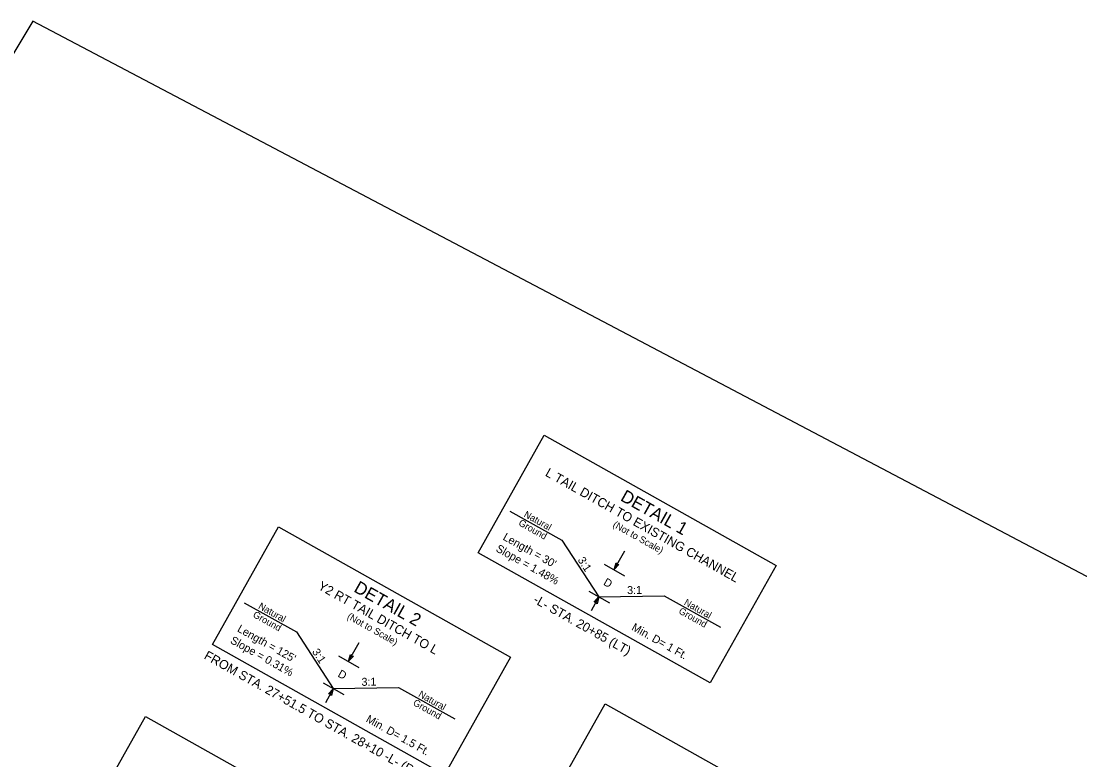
# Model space of a CAD drawing. Extents: x 2283629 to 2286552, y 529718 to 531440.
# Drawn here: x 2284113 to 2284634, y 531076 to 531440 of the extents above; entities that cross this region are included whole.
import ezdxf

# ---------------------------------------------------------------- set-up
doc = ezdxf.new("R2010")
doc.units = 0
for name, color, linetype in [('_CIVIL_CONSTRUCTION', 7, 'Continuous'), ('P_NCDOT_Terrain_Breakline', 7, 'Continuous'), ('P_NCDOT_Terrain_Hole', 7, 'Continuous')]:
    doc.layers.add(name, color=color, linetype=linetype)

msp = doc.modelspace()

# ---------------------------------------------------------------- linework, layer by layer
at = {"layer": '_CIVIL_CONSTRUCTION'}
msp.add_lwpolyline([(2284118.64, 531439.85), (2283629.48, 530625.47), (2284052.7, 530374.01), (2284693.86, 529987.87), (2284931.04, 529916.94), (2285004.15, 530031.44), (2284997.45, 530131.22), (2285008.79, 530131.98), (2285237.08, 530763.31), (2284930.09, 531012.33)], close=True, dxfattribs=at)
at = {"layer": 'P_NCDOT_Terrain_Breakline'}
for points in [[(2284400.44, 531103.96), (2284526.11, 531033.42), (2284494.1, 530976.4), (2284368.43, 531046.94), (2284400.44, 531103.96)], [(2284174.2, 531097.74), (2284299.87, 531027.2), (2284267.86, 530970.18), (2284142.19, 531040.72), (2284174.2, 531097.74)]]:
    msp.add_lwpolyline(points, dxfattribs=at)
at = {"layer": 'P_NCDOT_Terrain_Hole'}
for p, q in [((2284404.86, 531169.95), (2284410.02, 531179.14)), ((2284399.84, 531172.59), (2284409.93, 531166.92)), ((2284392.38, 531159.29), (2284402.47, 531153.63)), ((2284397.29, 531156.47), (2284393.44, 531149.6)), ((2284274.13, 531124.81), (2284279.29, 531134)), ((2284269.11, 531127.44), (2284279.2, 531121.78)), ((2284261.65, 531114.15), (2284271.74, 531108.48)), ((2284266.56, 531111.33), (2284262.71, 531104.46))]:
    msp.add_line(p, q, dxfattribs=at)
for points in [[(2284370.4, 531236.09), (2284484.57, 531172), (2284452.1, 531114.16), (2284337.93, 531178.25), (2284370.4, 531236.09)], [(2284353.49, 531198.72), (2284379.12, 531184.42), (2284397.32, 531156.52), (2284429.45, 531157.08), (2284457.17, 531141.63)], [(2284239.67, 531190.94), (2284353.84, 531126.86), (2284321.37, 531069.02), (2284207.2, 531133.1), (2284239.67, 531190.94)], [(2284222.76, 531153.58), (2284248.39, 531139.28), (2284266.59, 531111.38), (2284298.72, 531111.93), (2284326.44, 531096.49)]]:
    msp.add_lwpolyline(points, dxfattribs=at)
for points in [[(2284407.19, 531172.43), (2284404.86, 531169.95), (2284405.75, 531173.26), (2284406.28, 531172.48)], [(2284394.96, 531153.98), (2284397.29, 531156.47), (2284396.4, 531153.15), (2284395.87, 531153.94)], [(2284276.46, 531127.29), (2284274.13, 531124.81), (2284275.02, 531128.12), (2284275.55, 531127.34)], [(2284264.23, 531108.84), (2284266.56, 531111.33), (2284265.67, 531108.01), (2284265.14, 531108.79)]]:
    msp.add_lwpolyline(points, close=True, dxfattribs=at)

# ---------------------------------------------------------------- texts
for s, height, rotation, p in [('L TAIL DITCH TO EXISTING CHANNEL', 4.4997, 330.6931, (2284370.53, 531216.32)), ('DETAIL 1', 6.187, 330.6931, (2284407.48, 531204.2)), ('Natural', 3.375, 330.6931, (2284360.08, 531196.15)), ('Ground', 3.375, 330.6931, (2284357.43, 531191.96)), ('(Not to Scale)', 3.375, 330.6931, (2284403.82, 531191.15)), ("Length = 30'", 3.9374, 330.6931, (2284349.7, 531184.85)), ('Slope = 1.48%', 3.9374, 330.6931, (2284346.25, 531179.15)), ('3:1', 3.937, 302.9443, (2284386.69, 531174.69)), ('Y2 RT TAIL DITCH TO L', 4.4997, 330.6931, (2284258.68, 531160.57)), ('DETAIL 2', 6.187, 330.6931, (2284276.25, 531159.33)), ('D', 3.94, 330.6931, (2284399.17, 531162.63)), ('3:1', 3.937, 0.9813, (2284411.23, 531157.88)), ('-L- STA. 20+85 (LT)', 4.5, 330.6931, (2284364.63, 531153.91)), ('Natural', 3.375, 330.6931, (2284229.35, 531151)), ('Ground', 3.375, 330.6931, (2284436.22, 531148.6)), ('Natural', 3.375, 330.6931, (2284438.87, 531152.79)), ('Ground', 3.375, 330.6931, (2284226.7, 531146.81)), ('(Not to Scale)', 3.375, 330.6931, (2284273.09, 531146.01)), ("Length = 125'", 3.9374, 330.6931, (2284218.97, 531139.71)), ('Min. D= 1 Ft.', 3.9374, 330.6931, (2284413.04, 531140.43)), ('Slope = 0.31%', 3.9374, 330.6931, (2284215.52, 531134.01)), ('3:1', 3.937, 302.9443, (2284255.96, 531129.55)), ('FROM STA. 27+51.5 TO STA. 28+10 -L- (RT)', 4.5, 330.6931, (2284202.59, 531126.34)), ('D', 3.94, 330.6931, (2284268.44, 531117.49)), ('3:1', 3.937, 0.9813, (2284280.5, 531112.74)), ('Natural', 3.375, 330.6931, (2284308.14, 531107.65)), ('Ground', 3.375, 330.6931, (2284305.49, 531103.46)), ('Min. D= 1.5 Ft.', 3.9374, 330.6931, (2284282.31, 531095.29))]:
    msp.add_text(s, height=height, rotation=rotation, dxfattribs=at).set_placement(p)

doc.saveas('drawing.dxf')
